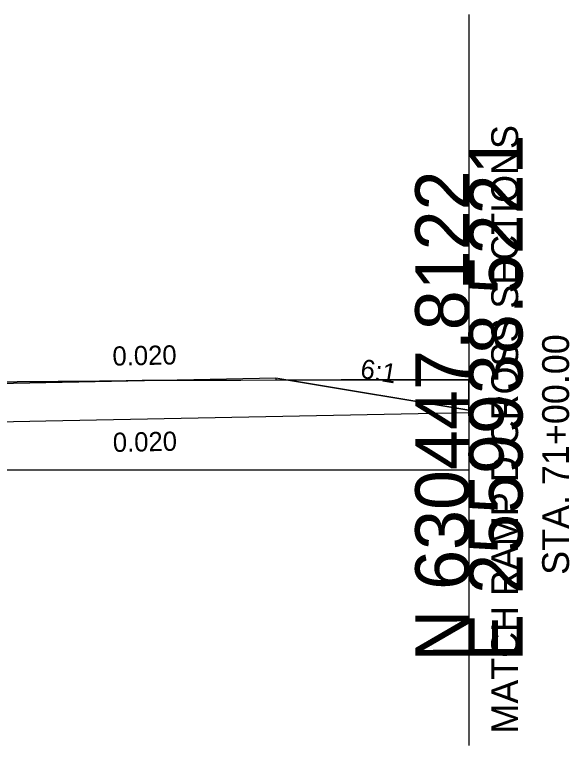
# Model space of a CAD drawing. Extents: x -985277 to -985025, y -985274 to -981226.
# Drawn here: x -985125.26 to -985096.32, y -983766 to -983727.9 of the extents above; entities that cross this region are included whole.
import ezdxf

# ---------------------------------------------------------------- set-up
doc = ezdxf.new("R2010")
doc.units = 0
for name, color, linetype in [('DESIGN - EARTHWORK - Excavation Limit Lines', 7, 'Continuous'), ('DESIGN - SHEET - Light Grid', 7, 'Continuous'), ('DESIGN - TYPICAL - Bridge Deck Median Barriers', 7, 'Continuous'), ('DESIGN - TYPICAL - Finished Grade and Subgrade', 7, 'Continuous'), ('DESIGN - TYPICAL - Side Slope to Bench Text', 7, 'Continuous'), ('DESIGN - TYPICAL - Warning Text', 7, 'Continuous'), ('SURVEY - AERIAL SURVEY - Mapping Setup - MAPPING LIMITS', 7, 'Continuous'), ('SURVEY - CONTROL - Check Points', 7, 'Continuous')]:
    doc.layers.add(name, color=color, linetype=linetype)

msp = doc.modelspace()

# ---------------------------------------------------------------- linework, layer by layer
at = {"layer": 'DESIGN - EARTHWORK - Excavation Limit Lines'}
msp.add_line((-985101.567, -983727.901), (-985101.567, -983765.999), dxfattribs=at)
at = {"layer": 'DESIGN - SHEET - Light Grid'}
msp.add_line((-985137.635, -983751.635), (-985101.567, -983751.635), dxfattribs=at)
at = {"layer": 'DESIGN - TYPICAL - Bridge Deck Median Barriers'}
for p, q in [((-985137.635, -983747.36), (-985123.635, -983747.08)), ((-985123.635, -983747.08), (-985111.635, -983746.84)), ((-985111.635, -983746.84), (-985111.635, -983746.953)), ((-985111.635, -983746.84), (-985101.567, -983748.518)), ((-985123.635, -983749.08), (-985101.567, -983748.639)), ((-985137.635, -983749.36), (-985123.635, -983749.08))]:
    msp.add_line(p, q, dxfattribs=at)
at = {"layer": 'DESIGN - TYPICAL - Finished Grade and Subgrade'}
for p, q in [((-985123.635, -983747.08), (-985137.635, -983747.36)), ((-985118.619, -983746.98), (-985123.635, -983747.08)), ((-985101.567, -983748.518), (-985110.972, -983746.951)), ((-985110.972, -983746.951), (-985101.567, -983748.518)), ((-985101.567, -983748.518), (-985101.567, -983746.937)), ((-985101.567, -983748.639), (-985101.567, -983748.518)), ((-985123.635, -983749.08), (-985101.567, -983748.639)), ((-985137.635, -983749.36), (-985123.635, -983749.08))]:
    msp.add_line(p, q, dxfattribs=at)
for points in [[(-985110.972, -983746.951), (-985111.635, -983746.953), (-985118.619, -983746.98)], [(-985101.567, -983746.937), (-985105.705, -983746.933), (-985106.66, -983746.934), (-985108.233, -983746.94), (-985110.972, -983746.951)]]:
    msp.add_lwpolyline(points, dxfattribs=at)
at = {"layer": 'SURVEY - AERIAL SURVEY - Mapping Setup - MAPPING LIMITS'}
msp.add_lwpolyline([(-985129.446, -983747.057), (-985118.696, -983746.98), (-985108.233, -983746.94), (-985106.66, -983746.934), (-985105.705, -983746.933), (-985101.567, -983746.937)], dxfattribs=at)

# ---------------------------------------------------------------- texts
at = {"layer": 'DESIGN - SHEET - Light Grid'}
for s, p in [('E 2559938.5221', (-985098.767, -983761.635)), ('N 630447.8122', (-985101.567, -983761.635))]:
    msp.add_text(s, height=2.8, rotation=90, dxfattribs=at).set_placement(p)
at = {"layer": 'DESIGN - TYPICAL - Side Slope to Bench Text'}
msp.add_text('0.020', height=1, rotation=1.1458, dxfattribs=at).set_placement((-985120.131, -983750.703))
at = {"layer": 'DESIGN - TYPICAL - Warning Text'}
for s, p in [('MATCH RAMP D CROSS SECTIONS', (-985098.998, -983765.384)), ('STA. 71+00.00', (-985096.344, -983757.108))]:
    msp.add_text(s, height=1.4, rotation=90, dxfattribs=at).set_placement(p)
at = {"layer": 'SURVEY - CONTROL - Check Points'}
for s, rotation, p in [('0.020', 1.1458, (-985120.151, -983746.203)), ('6:1', 350.5377, (-985107.277, -983746.827))]:
    msp.add_text(s, height=1, rotation=rotation, dxfattribs=at).set_placement(p)

doc.saveas('drawing.dxf')
